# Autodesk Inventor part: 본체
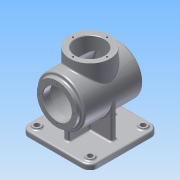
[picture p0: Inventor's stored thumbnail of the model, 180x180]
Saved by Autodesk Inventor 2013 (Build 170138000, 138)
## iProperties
Created: 2015-07
Part Number: 본체
Material: 알루미늄 6061
Document SubType Name: Modeling
Designer: Administrator
Density: 2.71 g/cm^3
Mass: 1276.08 g
Surface Area: 1271.73 cm^2
Volume: 470.878 cm^3
Author: Administrator
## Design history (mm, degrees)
sketch "스케치1"
  geometry: C1 r 45 at (0, 0); 1 further point
  constraints: 1 centre point, 1 coincident
  dimensions: "d0" = 90 diameter of C1
extrude "돌출1" new body sketch "스케치1" stored distance "d2" = 110; taper "d3" = 0 deg
sketch "스케치3"
  geometry: C1 r 38 at (0, 0); 1 further point
  constraints: 1 centre point, 1 coincident
  dimensions: "d162" = 76 diameter of C1
extrude "돌출2" join sketch "스케치3" distance "d6" = 62; taper "d7" = 0 deg
node "작업 평면1"
sketch "스케치4"
  geometry: L1 (-50, 65)-(50, 65); L2 (65, 50)-(65, -50); L3 (50, -65)-(-50, -65); L4 (-65, -50)-(-65, 50); A1 r 15 centre (-50, 50) between (-50, 65) and (-65, 50); A2 r 15 centre (-50, -50) between (-65, -50) and (-50, -65); A3 r 15 centre (50, -50) between (50, -65) and (65, -50); A4 r 15 centre (50, 50) between (65, 50) and (50, 65); 3 further points
  constraints: 8 end point, 8 point on circle, 8 tangent, 4 centre point, 3 equal radius, 2 midpoint, 2 parallel, 2 perpendicular, 1 horizontal, 1 horizontal alignment, 1 vertical alignment
  dimensions: "d9" = 130 distance between parallel lines of L4 L2; "d11" = 15 radius of A1
extrude "돌출3" join sketch "스케치4" distance "d12" = 10; taper "d13" = 0 deg
sketch "스케치5"
  geometry: L1 (45, 55)-(-45, 55) reference; L2 (-45, -55)-(-45, 55) reference; L3 (45, -55)-(45, 55) reference; L4 (-45, -55)-(45, -55) reference; L5 (-5, 45)-(5, 45); L6 (5, 45)-(5, -45); L7 (5, -45)-(-5, -45); L8 (-5, -45)-(-5, 45); L9 (-45, 5)-(45, 5); L10 (45, 5)-(45, -5); L11 (45, -5)-(-45, -5); L12 (-45, -5)-(-45, 5); 6 further points
  constraints: 16 end point, 5 midpoint, 4 parallel, 2 horizontal, 2 horizontal alignment, 2 perpendicular, 2 vertical alignment
  dimensions: "d14" = 90 distance between parallel lines of L7 L5; "d16" = 10 distance between parallel lines of L8 L6; "d17" = 10 distance between parallel lines of L11 L9; "d18" = 90 distance between parallel lines of L12 L10
extrude "돌출4" join sketch "스케치5" distance "d19" = 78; taper "d20" = 0 deg
sketch "스케치6"
  geometry: L1 (-45, -55)-(45, -55) reference; L2 (0, -48)-(0, 48); L3 (0, -48)-(40, -48); L4 (40, -48)-(40, 48); L5 (40, 48)-(0, 48); 2 further points
  constraints: 8 end point, 3 perpendicular, 1 midpoint, 1 parallel, 1 point on line
  dimensions: "d30" = 96 distance of L2.start L2.end; "d32" = 7 distance between parallel lines of L3 L1; "d33" = 80 diameter of L4 L2
revolve "회전1" sketch "스케치6" stored, may be unused: angle "d34" = 90 deg
sketch "스케치9"
  geometry: C1 r 7.5 at (-50, 50); C2 r 7.5 at (50, 50); C3 r 7.5 at (50, -50); C4 r 7.5 at (-50, -50); 1 further point
  constraints: 4 centre point, 3 equal radius, 2 horizontal alignment, 2 vertical alignment
  dimensions: "d62" = 100 distance of C1.centre C2.centre; "d64" = 50 horizontal distance of point (0, 0) C2.centre; "d65" = 100 distance of C3.centre C2.centre; "d66" = 50 horizontal distance of point (0, 0) C3.centre; "d67" = 15 diameter of C2
extrude "돌출6" join sketch "스케치9" distance "d68" = 3; taper "d69" = 0 deg
hole "구멍4" diameter "d72" = 10; stored, may be unused: countersink angle "d76" = 90 deg, drill point angle "d78" = 0 deg; dims "d70" = 10, "d71" = 10, "d73" = 6, "d74" = 54, "d75" = 14, "d77" = 14
hole "구멍5" diameter "d81" = 10; stored, may be unused: countersink angle "d85" = 90 deg, drill point angle "d87" = 0 deg; dims "d79" = 10, "d80" = 10, "d82" = 6, "d83" = 54, "d84" = 14, "d86" = 14
hole "구멍6" diameter "d90" = 10; stored, may be unused: countersink angle "d94" = 90 deg, drill point angle "d96" = 0 deg; dims "d88" = 10, "d89" = 10, "d91" = 6, "d92" = 54, "d93" = 14, "d95" = 14
hole "구멍7" diameter "d99" = 10; stored, may be unused: countersink angle "d103" = 90 deg, drill point angle "d105" = 0 deg; dims "d97" = 10, "d98" = 10, "d100" = 6, "d101" = 54, "d102" = 14, "d104" = 14
sketch "스케치10"
  geometry: C1 r 38 at (0, 0); 1 further point
  constraints: 1 centre point, 1 coincident
  dimensions: "d106" = 76 diameter of C1
extrude "돌출7" join sketch "스케치10" distance "d108" = 7; taper "d109" = 0 deg
hole "구멍8" diameter "d112" = 54; stored, may be unused: countersink angle "d116" = 90 deg, drill point angle "d118" = 0 deg; dims "d110" = 10, "d111" = 10, "d113" = 6, "d114" = 54, "d115" = 14, "d117" = 14
sketch "스케치11"
  geometry: A1 r 32 centre (0, 0) between (0, 32) and (0, -32); 3 further points
  constraints: 4 point on circle, 2 horizontal alignment, 2 vertical alignment, 1 centre point, 1 coincident
  dimensions: "d119" = 64 diameter of A1
hole "구멍9" sketch "스케치11" at (0, 32), (0, -32), (32, 0), (-32, 0) diameter "d121" = 3.242; stored, may be unused: countersink angle "d125" = 90 deg, drill point angle "d127" = 118 deg; dims "d122" = 8, "d123" = 54, "d124" = 14, "d126" = 10
sketch "스케치13"
  geometry: L1 (-24.887, 3.602)-(24.887, 3.602); L2 (24.887, 3.602)-(24.887, -3.602); L3 (24.887, -3.602)-(-24.887, -3.602); L4 (-24.887, -3.602)-(-24.887, 3.602); 6 further points
  constraints: 4 midpoint, 2 horizontal alignment, 2 vertical alignment, 1 coincident, 2 other
  dimensions: "d137" = 49.77477 distance between parallel lines of L2 L4; "d138" = 7.20489 distance between parallel lines of L3 L1
feature "엠보싱1" sketch "스케치13" dims "d2" = 110, "d139" = 0.5, "d140" = 0
fillet "모깎기1" dims "d141" = 3
fillet "모깎기2" dims "d142" = 3
fillet "모깎기4" dims "d144" = 3
fillet "모깎기5" dims "d145" = 3
fillet "모깎기7" dims "d147" = 3
fillet "모깎기8" dims "d151" = 3
fillet "모깎기9" dims "d152" = 3
fillet "모깎기10" dims "d153" = 3
chamfer "모따기2" distance "d154" = 1; stored, may be unused: second distance "d155" = 2, angle "d156" = 45 deg
hole "구멍11" diameter "d167" = 54; stored, may be unused: countersink angle "d171" = 90 deg, drill point angle "d173" = 0 deg; dims "d165" = 10, "d166" = 10, "d168" = 6, "d169" = 4, "d170" = 2, "d172" = 50
sketch "스케치14"
  geometry: A1 r 32 centre (0, 0) between (0, 32) and (0, -32); 3 further points
  constraints: 4 point on circle, 2 horizontal alignment, 2 vertical alignment, 1 centre point, 1 coincident
  dimensions: "d176" = 64 diameter of A1
hole "구멍12" sketch "스케치14" at (0, 32), (0, -32), (32, 0), (-32, 0) diameter "d178" = 3.242; stored, may be unused: countersink angle "d182" = 90 deg, drill point angle "d184" = 0 deg; dims "d179" = 8, "d180" = 4, "d181" = 2, "d183" = 10
chamfer "모따기4" distance "d185" = 1; stored, may be unused: second distance "d186" = 2, angle "d187" = 45 deg
fillet "모깎기11" dims "d188" = 3
fillet "모깎기12" dims "d189" = 3
node "솔리드1"
